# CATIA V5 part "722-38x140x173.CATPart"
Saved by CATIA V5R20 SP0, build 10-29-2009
Part number: 722-38x140x173
Definition: NONE
Nomenclature: 722-38x140x173
Source: Unknown
Description: 722-38x140x173
Bounding box of the stored display mesh (mm): x -19 to 19, y -18.807 to 18.807, z -125 to 48
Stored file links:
  C:\Users\Utente\Desktop\IO LAVORO\3D X SITO CF\X SITO\722\722-38x140x173.CATPart

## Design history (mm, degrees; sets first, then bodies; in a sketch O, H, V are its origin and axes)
Body1 "722-38x140x173" (main body)
  Solid1: solid without history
